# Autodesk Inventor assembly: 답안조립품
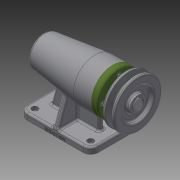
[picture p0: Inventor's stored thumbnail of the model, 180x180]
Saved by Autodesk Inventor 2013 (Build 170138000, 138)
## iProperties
Created: 2018-09
Part Number: 답안조립품
Document SubType Name: Assembly
Designer: Administrator
Author: Administrator
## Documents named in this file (12)
- C:\Users\Administrator\Desktop\480908V1004\답안조립품.iam
- C:\Users\Administrator\Desktop\480908V1004\본체.ipt
- C:\Users\Administrator\Desktop\480908V1004\축.ipt
- C:\Users\Administrator\Desktop\480908V1004\키 5 x 5 x 16.ipt
- C:\Users\Administrator\Desktop\480908V1004\멈춤나사 M3.ipt
- C:\Users\Administrator\Desktop\480908V1004\V벨트풀리.ipt
- C:\Users\Administrator\Desktop\480908V1004\커버.ipt
- C:\Users\Administrator\Desktop\480908V1004\오일 실.ipt
- C:\Users\Administrator\Desktop\480908V1004\베어링 6004.ipt
- C:\Users\Administrator\Desktop\480908V1004\볼트 M4.ipt
- C:\Users\Administrator\Desktop\480908V1004\베어링 51202.ipt
- C:\Users\Administrator\Desktop\480908V1004\어댑터슬리브.ipt
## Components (1 placed, 1 different names)
1. V벨트풀리:1 — 각도:2
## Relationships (1: Angle 1)
- 각도:2 [Angle]: V벨트풀리:1
